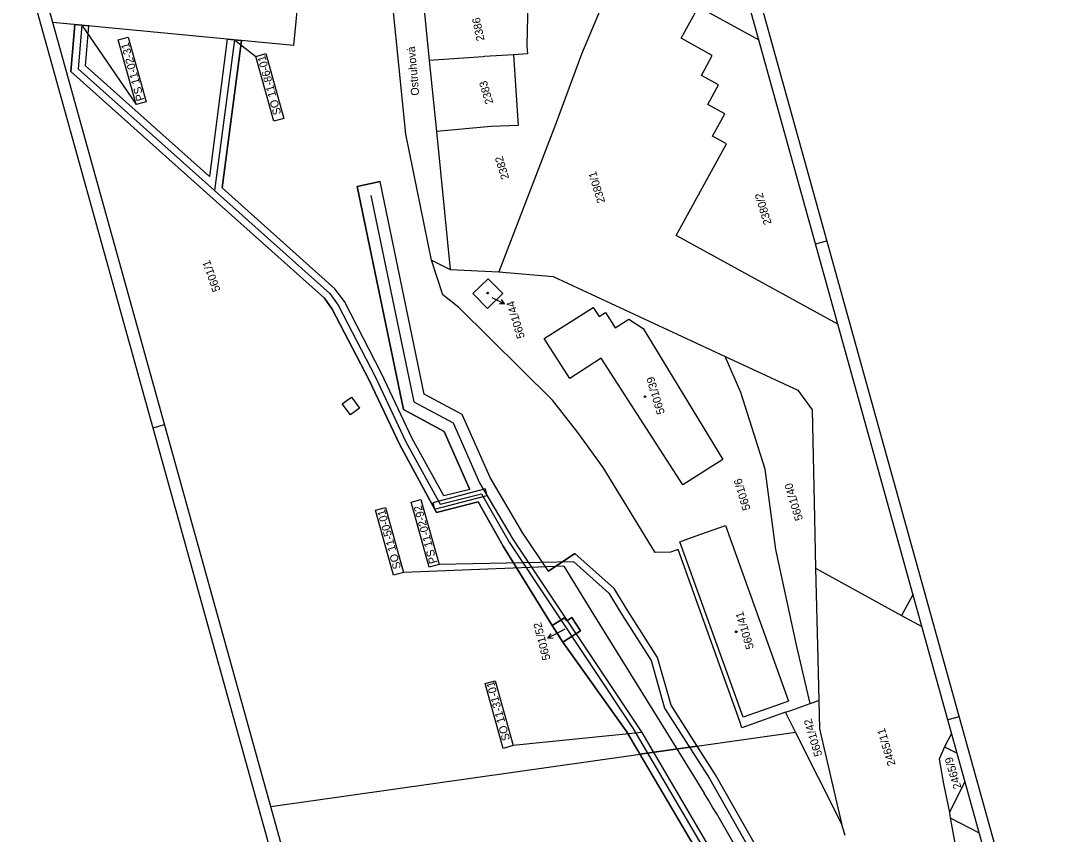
# Model space of a CAD drawing. Extents: x -821057 to -820632, y -1070881 to -1069829.
# Drawn here: x -821000.4 to -820778.2, y -1070259 to -1070086.2 of the extents above; entities that cross this region are included whole.
import ezdxf

# ---------------------------------------------------------------- set-up
doc = ezdxf.new("R2010")
doc.units = 0
for name, color, linetype in [('_PS_SO_číslo', 7, 'Continuous'), ('DZ_hranice_NAD_bez rozlišení', 7, 'Continuous'), ('DZ_NAD_ostatní', 7, 'Continuous'), ('DZ_NAD_UMVZST', 7, 'Continuous'), ('Hranice kat_území', 7, 'Continuous'), ('Hranice parcel', 7, 'Continuous'), ('Parcelní čísla', 7, 'Continuous'), ('Pop  PČ popisy', 7, 'Continuous'), ('PS-11-02-31', 7, 'Continuous'), ('PS-11-02-41', 7, 'Continuous'), ('PS-11-02-92', 7, 'Continuous'), ('Rám', 7, 'Continuous'), ('SO-11-31-01', 7, 'Continuous'), ('SO-11-50-01', 7, 'Continuous'), ('SO-11-86-01', 7, 'Continuous'), ('Vnitřní kresba', 7, 'Continuous'), ('Značky budov', 7, 'Continuous')]:
    doc.layers.add(name, color=color, linetype=linetype)

msp = doc.modelspace()

# ---------------------------------------------------------------- linework, layer by layer
at = {"layer": '_PS_SO_číslo'}
for p, q in [((-820987.51, -1070087.08), (-820975.94, -1070103.97)), ((-820955.09, -1070090.19), (-820950.53, -1070093.71)), ((-820882.99, -1070201.13), (-820911.61, -1070201.67)), ((-820885.11, -1070202.07), (-820919.13, -1070203.37)), ((-820868.5, -1070237.37), (-820895.88, -1070240.18))]:
    msp.add_line(p, q, dxfattribs=at)
for points in [[(-820977.64, -1070089.6), (-820973.82, -1070103.38), (-820975.94, -1070103.97), (-820979.76, -1070090.19)], [(-820948.41, -1070093.12), (-820944.58, -1070106.9), (-820946.7, -1070107.49), (-820950.53, -1070093.71)], [(-820915.44, -1070187.9), (-820911.61, -1070201.67), (-820913.73, -1070202.26), (-820917.56, -1070188.48)], [(-820922.96, -1070189.59), (-820919.13, -1070203.37), (-820921.25, -1070203.96), (-820925.08, -1070190.18)], [(-820899.71, -1070226.4), (-820895.88, -1070240.18), (-820898, -1070240.77), (-820901.83, -1070226.99)]]:
    msp.add_lwpolyline(points, close=True, dxfattribs=at)
at = {"layer": 'DZ_hranice_NAD_bez rozlišení'}
for p, q in [((-820989.01, -1070086.94), (-820986.02, -1070087.23)), ((-820956.59, -1070090.05), (-820960.4, -1070119.21)), ((-820953.6, -1070090.34), (-820957.69, -1070121.63)), ((-820956.59, -1070090.05), (-820953.6, -1070090.34)), ((-820929.03, -1070121.35), (-820924.13, -1070120.33)), ((-820888.38, -1070203.11), (-820882.74, -1070199.34))]:
    msp.add_line(p, q, dxfattribs=at)
for points in [[(-820843.48, -1070284.13), (-820843.93, -1070282.84), (-820847.81, -1070277.93), (-820871.73, -1070237.25), (-820885.29, -1070218.2), (-820887.54, -1070214.67), (-820897.96, -1070197.77), (-820903.32, -1070188.38), (-820912.12, -1070190.61), (-820919.97, -1070176.29), (-820926.49, -1070162.4), (-820934.28, -1070147.4), (-820935.96, -1070145.11), (-820960.28, -1070123.34), (-820989.85, -1070096.95), (-820989.01, -1070086.94)], [(-820960.4, -1070119.21), (-820986.73, -1070095.71), (-820986.02, -1070087.23)], [(-820905.06, -1070185.73), (-820910.61, -1070187.13), (-820917.29, -1070174.93), (-820923.8, -1070161.07), (-820931.72, -1070145.81), (-820933.72, -1070143.08), (-820957.69, -1070121.63)], [(-820905.06, -1070185.73), (-820905.22, -1070185.45), (-820910.55, -1070173.4), (-820919.16, -1070168.77), (-820929.03, -1070121.35)], [(-820888.38, -1070203.11), (-820893.8, -1070195), (-820900.76, -1070183.17), (-820906.67, -1070169.8), (-820914.74, -1070165.47), (-820924.13, -1070120.33)], [(-820833.99, -1070279.04), (-820843.49, -1070262.96), (-820852.87, -1070246.42), (-820862.31, -1070231.6), (-820865.19, -1070221.48), (-820871.51, -1070211.52), (-820874.37, -1070206.78), (-820882.74, -1070199.34)]]:
    msp.add_lwpolyline(points, dxfattribs=at)
at = {"layer": 'DZ_NAD_ostatní'}
for points in [[(-820885.29, -1070218.2), (-820881.58, -1070215.81), (-820883.39, -1070212.98), (-820884.49, -1070213.68), (-820884.92, -1070213), (-820887.54, -1070214.67)], [(-820887.54, -1070214.67), (-820886.5, -1070216.3), (-820885.29, -1070218.2)]]:
    msp.add_lwpolyline(points, dxfattribs=at)
at = {"layer": 'DZ_NAD_UMVZST'}
for p, q in [((-820986.02, -1070087.23), (-820989.01, -1070086.94)), ((-820956.59, -1070090.05), (-820960.4, -1070119.21)), ((-820957.69, -1070121.63), (-820953.6, -1070090.34)), ((-820953.6, -1070090.34), (-820956.59, -1070090.05)), ((-820924.13, -1070120.33), (-820929.03, -1070121.35)), ((-820882.74, -1070199.34), (-820888.38, -1070203.11)), ((-820856.78, -1070240.29), (-820868.93, -1070242.01)), ((-820868.93, -1070242.01), (-820856.78, -1070240.29))]:
    msp.add_line(p, q, dxfattribs=at)
for points in [[(-820989.01, -1070086.94), (-820989.85, -1070096.95), (-820960.28, -1070123.34), (-820935.96, -1070145.11), (-820934.28, -1070147.4), (-820926.49, -1070162.4), (-820919.97, -1070176.29), (-820912.12, -1070190.61), (-820903.32, -1070188.38), (-820897.96, -1070197.77), (-820887.54, -1070214.67)], [(-820960.4, -1070119.21), (-820986.73, -1070095.71), (-820986.02, -1070087.23)], [(-820905.06, -1070185.73), (-820910.61, -1070187.13), (-820917.29, -1070174.93), (-820923.8, -1070161.07), (-820931.72, -1070145.81), (-820933.72, -1070143.08), (-820957.69, -1070121.63)], [(-820929.03, -1070121.35), (-820919.16, -1070168.77), (-820910.55, -1070173.4), (-820905.22, -1070185.45), (-820905.06, -1070185.73)], [(-820888.38, -1070203.11), (-820893.8, -1070195), (-820900.76, -1070183.17), (-820906.67, -1070169.8), (-820914.74, -1070165.47), (-820924.13, -1070120.33)], [(-820856.78, -1070240.29), (-820862.31, -1070231.6), (-820865.19, -1070221.48), (-820871.51, -1070211.52), (-820874.37, -1070206.78), (-820882.74, -1070199.34)], [(-820887.54, -1070214.67), (-820884.92, -1070213), (-820884.49, -1070213.68), (-820883.39, -1070212.98), (-820881.58, -1070215.81), (-820885.29, -1070218.2)], [(-820885.29, -1070218.2), (-820871.73, -1070237.25), (-820868.93, -1070242.01)], [(-820833.99, -1070279.04), (-820843.49, -1070262.96), (-820852.87, -1070246.42), (-820856.78, -1070240.29)], [(-820868.93, -1070242.01), (-820847.81, -1070277.93), (-820843.93, -1070282.84), (-820843.48, -1070284.13)]]:
    msp.add_lwpolyline(points, dxfattribs=at)
at = {"layer": 'Hranice kat_území'}
for p, q in [((-820887.52, -1070166.75), (-820907.37, -1070147.11)), ((-820847.74, -1070235.07), (-820860.8, -1070198.48)), ((-820835.88, -1070237.32), (-820838.01, -1070233.1)), ((-820826.1, -1070256.7), (-820835.88, -1070237.32)), ((-820825.3, -1070259.25), (-820826.1, -1070256.7))]:
    msp.add_line(p, q, dxfattribs=at)
for points in [[(-820913.23, -1070137.01), (-820918.68, -1070110.25), (-820922.83, -1070068.79), (-820922.62, -1070052.45)], [(-820907.37, -1070147.11), (-820910.8, -1070144.4), (-820913.23, -1070137.01)], [(-820860.8, -1070198.48), (-820862.44, -1070199.07), (-820865.67, -1070199.11), (-820876.76, -1070181.11), (-820882.1, -1070173.67), (-820887.52, -1070166.75)], [(-820838.01, -1070233.1), (-820846.3, -1070236.05), (-820847.27, -1070236.4), (-820847.74, -1070235.07)]]:
    msp.add_lwpolyline(points, dxfattribs=at)
at = {"layer": 'Hranice parcel'}
for p, q in [((-820914.97, -1070081.64), (-820913.68, -1070094.59)), ((-820843.69, -1070090.21), (-820843.69, -1070090.21)), ((-820913.68, -1070094.59), (-820912.16, -1070109.68)), ((-820913.23, -1070137.01), (-820909.27, -1070138.99)), ((-820909.27, -1070138.99), (-820898.88, -1070139.5)), ((-820826.9, -1070150.65), (-820826.9, -1070150.65)), ((-820831.6, -1070202.47), (-820813.34, -1070212.53)), ((-820810.93, -1070208.13), (-820813.34, -1070212.53)), ((-820810.93, -1070208.13), (-820810.93, -1070208.13)), ((-820813.34, -1070212.53), (-820809.06, -1070214.86)), ((-820809.06, -1070214.86), (-820809.06, -1070214.86)), ((-820832.77, -1070231.24), (-820830.93, -1070230.58)), ((-820947.35, -1070253.15), (-820835.88, -1070237.32)), ((-820802.74, -1070237.6), (-820804.2, -1070240.46)), ((-820802.74, -1070237.6), (-820802.74, -1070237.6)), ((-820801.57, -1070241.78), (-820801.57, -1070241.78)), ((-820799.9, -1070247.81), (-820799.9, -1070247.81)), ((-820803.2, -1070254.4), (-820803, -1070255.5)), ((-820803, -1070255.5), (-820801.94, -1070261.25)), ((-820796.87, -1070258.72), (-820796.87, -1070258.72))]:
    msp.add_line(p, q, dxfattribs=at)
for points in [[(-820988.25, -1070070.69), (-820940.94, -1070075.3), (-820942.5, -1070091.4)], [(-820877.39, -1070083.81), (-820881.36, -1070093.26), (-820886.87, -1070108.2), (-820898.88, -1070139.5)], [(-820878.59, -1070083.2), (-820892.71, -1070082.07), (-820892.93, -1070091.44), (-820892.8, -1070093.17), (-820895.78, -1070093.35)], [(-820826.9, -1070150.65), (-820861.21, -1070131.75), (-820850.55, -1070112.3), (-820853.49, -1070110.66), (-820850.87, -1070105.91), (-820854.53, -1070103.94), (-820852.21, -1070099.75), (-820855.86, -1070097.75), (-820853.56, -1070093.52), (-820860.16, -1070089.86), (-820856.47, -1070083.21), (-820843.69, -1070090.21)], [(-820942.5, -1070091.4), (-820993.66, -1070086.49)], [(-820895.78, -1070093.35), (-820901.94, -1070093.75), (-820902.26, -1070093.79), (-820913.68, -1070094.59)], [(-820895.78, -1070093.35), (-820894.81, -1070108.42), (-820900.5, -1070108.58), (-820912.16, -1070109.68)], [(-820912.16, -1070109.68), (-820910.42, -1070126.82), (-820909.27, -1070138.99)], [(-820901.18, -1070140.95), (-820898.08, -1070144.08), (-820901.29, -1070147.27), (-820904.4, -1070144.11), (-820901.18, -1070140.95)], [(-820898.88, -1070139.5), (-820887.34, -1070140.5), (-820850.84, -1070157.46)], [(-820878.86, -1070147.05), (-820877.61, -1070149.01), (-820876.24, -1070148.14), (-820874.2, -1070151.37), (-820871.31, -1070149.54), (-820868.25, -1070151.57), (-820851.33, -1070179.37), (-820859.8, -1070184.75), (-820877.14, -1070157.82), (-820883.85, -1070162.18), (-820889.3, -1070153.67), (-820878.86, -1070147.05)], [(-820832.77, -1070231.24), (-820835.57, -1070219.11), (-820840.04, -1070198.5), (-820842.31, -1070181.46), (-820847.5, -1070165.14), (-820850.84, -1070157.46)], [(-820850.84, -1070157.46), (-820835.36, -1070164.66), (-820832.35, -1070168.8), (-820831.85, -1070191.82), (-820831.6, -1070202.47)], [(-820838.92, -1070231.3), (-820846.98, -1070234.17), (-820860.48, -1070196.84), (-820857.17, -1070195.66), (-820850.78, -1070193.39), (-820837.36, -1070230.75), (-820838.92, -1070231.3)], [(-820831.6, -1070202.47), (-820831.16, -1070221.77), (-820830.93, -1070230.58)], [(-820885.29, -1070218.2), (-820887.54, -1070214.67), (-820884.92, -1070213), (-820884.49, -1070213.68), (-820883.39, -1070212.98), (-820881.58, -1070215.81), (-820885.29, -1070218.2)], [(-820830.93, -1070230.58), (-820830.77, -1070236.59), (-820826.1, -1070256.7)], [(-820838.01, -1070233.1), (-820836.68, -1070232.63), (-820832.77, -1070231.24)], [(-820804.2, -1070240.46), (-820805.38, -1070243.04), (-820804.45, -1070248.28), (-820803.2, -1070254.4)], [(-820804.2, -1070240.46), (-820801.57, -1070241.78)], [(-820799.9, -1070247.81), (-820803.2, -1070254.4)], [(-820803, -1070255.5), (-820796.87, -1070258.72)]]:
    msp.add_lwpolyline(points, dxfattribs=at)
at = {"layer": 'Pop  PČ popisy'}
for p, q in [((-820900.36, -1070144.95), (-820897.67, -1070146.27)), ((-820897.67, -1070146.27), (-820898.35, -1070145.38)), ((-820897.67, -1070146.27), (-820898.79, -1070146.28)), ((-820885.81, -1070215.93), (-820888.46, -1070217.34)), ((-820888.46, -1070217.34), (-820887.81, -1070216.43)), ((-820884.86, -1070215.44), (-820885.81, -1070215.93)), ((-820888.46, -1070217.34), (-820887.34, -1070217.31))]:
    msp.add_line(p, q, dxfattribs=at)
at = {"layer": 'PS-11-02-31'}
for points in [[(-820987.51, -1070087.08), (-820988.29, -1070096.33), (-820959.28, -1070122.22)], [(-820959.28, -1070122.22), (-820934.84, -1070144.09), (-820933, -1070146.6), (-820925.15, -1070161.74), (-820918.63, -1070175.61), (-820911.37, -1070188.87), (-820902.58, -1070186.65), (-820896.69, -1070196.98), (-820870.46, -1070236.45), (-820846.57, -1070277.08), (-820842.6, -1070282.11), (-820813.47, -1070365.17), (-820809.8, -1070374.33), (-820792.8, -1070426.72), (-820792.34, -1070428.47), (-820790.08, -1070430.86), (-820788.92, -1070435.58), (-820780.39, -1070470.86), (-820770.55, -1070511.61), (-820767.89, -1070524.68), (-820765.3, -1070562.4), (-820759.61, -1070562.18)]]:
    msp.add_lwpolyline(points, dxfattribs=at)
at = {"layer": 'PS-11-02-41'}
msp.add_lwpolyline([(-820882.99, -1070201.13), (-820875.54, -1070207.75), (-820872.79, -1070212.31), (-820866.57, -1070222.1), (-820863.69, -1070232.23), (-820854.15, -1070247.2), (-820844.78, -1070263.71), (-820834.74, -1070280.72), (-820830.77, -1070287.4), (-820826.6, -1070295.78), (-820822.74, -1070307.42), (-820822.4, -1070310.54), (-820820.82, -1070316.36), (-820815.08, -1070335.82), (-820806.04, -1070362.21), (-820801.05, -1070374.78), (-820795.98, -1070387.28), (-820794.84, -1070388), (-820792.15, -1070393.19), (-820783.48, -1070412.23), (-820783.6, -1070416.46), (-820783.6, -1070418.02), (-820782.43, -1070424.35)], dxfattribs=at)
at = {"layer": 'PS-11-02-92'}
msp.add_lwpolyline([(-820882.99, -1070201.13), (-820875.54, -1070207.75), (-820872.79, -1070212.31), (-820866.57, -1070222.1), (-820863.69, -1070232.23), (-820854.15, -1070247.2), (-820844.78, -1070263.71), (-820834.74, -1070280.72), (-820830.77, -1070287.4), (-820826.6, -1070295.78), (-820822.74, -1070307.42), (-820822.4, -1070310.54), (-820820.82, -1070316.36), (-820815.08, -1070335.82), (-820806.04, -1070362.21), (-820801.05, -1070374.78), (-820795.98, -1070387.28), (-820794.84, -1070388), (-820792.15, -1070393.19), (-820783.48, -1070412.23), (-820783.6, -1070416.46), (-820783.6, -1070418.02), (-820782.43, -1070424.35)], dxfattribs=at)
at = {"layer": 'Rám'}
for p, q in [((-820993.66, -1070086.49), (-820993.66, -1070086.49)), ((-820992.83, -1070089.47), (-820992.83, -1070089.47)), ((-820992.55, -1070090.49), (-820992.55, -1070090.49)), ((-820990.53, -1070097.77), (-820990.53, -1070097.77)), ((-820989.95, -1070099.83), (-820989.95, -1070099.83)), ((-820831.65, -1070133.56), (-820829.24, -1070132.89)), ((-820972.32, -1070172.64), (-820969.91, -1070171.97)), ((-820801.13, -1070234.05), (-820803.54, -1070234.72)), ((-820947.35, -1070253.15), (-820947.35, -1070253.15))]:
    msp.add_line(p, q, dxfattribs=at)
for points in [[(-821000.43, -1070071.48), (-820857.35, -1070031.72), (-820632.46, -1070841.06), (-820775.54, -1070880.81)], [(-820997.35, -1070073.22), (-820859.09, -1070034.8), (-820635.54, -1070839.32), (-820773.8, -1070877.73)]]:
    msp.add_lwpolyline(points, close=True, dxfattribs=at)
at = {"layer": 'SO-11-31-01'}
msp.add_lwpolyline([(-820926.07, -1070123.29), (-820916.95, -1070167.12), (-820908.61, -1070171.6), (-820902.99, -1070184.31), (-820895.92, -1070196.33), (-820868.5, -1070237.37), (-820845.66, -1070276.46), (-820841.66, -1070281.51), (-820839.82, -1070285.2), (-820808.13, -1070374.18), (-820790.33, -1070426.97), (-820782.93, -1070433.41), (-820769.19, -1070488.5), (-820779.89, -1070491.4)], dxfattribs=at)
at = {"layer": 'SO-11-50-01'}
msp.add_lwpolyline([(-820885.11, -1070202.07), (-820878.77, -1070212.32), (-820861.83, -1070239.7), (-820855.27, -1070250.3)], dxfattribs=at)
msp.add_arc((-821067.95, -1070381.86), 250.08, 19.1742, 31.7407, dxfattribs=at)
at = {"layer": 'SO-11-86-01'}
for points in [[(-820955.09, -1070090.19), (-820959.28, -1070122.22), (-820934.84, -1070144.09), (-820933, -1070146.6), (-820925.15, -1070161.74), (-820918.63, -1070175.61), (-820911.37, -1070188.87), (-820902.58, -1070186.65), (-820896.69, -1070196.98), (-820870.46, -1070236.45), (-820846.57, -1070277.08)], [(-820882.99, -1070201.13), (-820875.54, -1070207.75), (-820872.79, -1070212.31), (-820866.57, -1070222.1), (-820863.69, -1070232.23), (-820854.15, -1070247.2), (-820844.78, -1070263.71)]]:
    msp.add_lwpolyline(points, dxfattribs=at)
msp.add_lwpolyline([(-820912.95, -1070188.59), (-820912.59, -1070189.95), (-820901.35, -1070187), (-820901.71, -1070185.64)], close=True, dxfattribs=at)
at = {"layer": 'Vnitřní kresba'}
for p, q in [((-820932.15, -1070167.55), (-820930.22, -1070166.12)), ((-820930.22, -1070166.12), (-820928.5, -1070168.46)), ((-820930.43, -1070169.88), (-820932.15, -1070167.55)), ((-820928.5, -1070168.46), (-820930.43, -1070169.88))]:
    msp.add_line(p, q, dxfattribs=at)
at = {"layer": 'Značky budov'}
for centre in [(-820901.26, -1070144.02), (-820867.85, -1070166.04), (-820848.47, -1070215.99)]:
    msp.add_circle(centre, 0.175, dxfattribs=at)

# ---------------------------------------------------------------- texts
at = {"layer": '_PS_SO_číslo'}
for s, p in [('PS 11-02-31', (-820974.16, -1070102.93)), ('SO 11-86-01', (-820945.11, -1070105.89)), ('SO 11-50-01', (-820919.65, -1070202.42)), ('PS 11-02-92', (-820911.97, -1070201.28)), ('SO 11-31-01', (-820896.49, -1070238.9))]:
    msp.add_text(s, height=1.7, rotation=105.5289, dxfattribs=at).set_placement(p)
at = {"layer": 'Parcelní čísla'}
for s, rotation, p in [('2386', 101.6994, (-820901.93, -1070090.27)), ('2383', 106.7086, (-820900.06, -1070103.59)), ('2382', 106.7086, (-820896.69, -1070119.59)), ('2380/1', 106.7086, (-820876.28, -1070124.65)), ('2380/2', 106.7086, (-820840.93, -1070129.22)), ('5601/1', 109.3088, (-820958.02, -1070143.41)), ('5601/44', 106.7086, (-820893.35, -1070153.39)), ('5601/39', 106.7086, (-820863.62, -1070169.5)), ('5601/6', 106.7086, (-820845.41, -1070189.92)), ('5601/40', 106.7086, (-820834.27, -1070192.1)), ('5601/41', 106.7086, (-820844.69, -1070219.41)), ('5601/52', 104.3527, (-820887.91, -1070221.81)), ('5601/42', 106.7086, (-820830.16, -1070242.2)), ('2465/11', 106.7086, (-820814.59, -1070244.22)), ('2465/9', 106.7086, (-820800.6, -1070249.11))]:
    msp.add_text(s, height=1.7, rotation=rotation, dxfattribs=at).set_placement(p)
at = {"layer": 'Pop  PČ popisy'}
msp.add_text('Ostruhová', height=1.7, rotation=95, dxfattribs=at).set_placement((-820915.82, -1070101.98))

doc.saveas('drawing.dxf')
